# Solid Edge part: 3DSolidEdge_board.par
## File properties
Author: Administrator
Last saved by: Administrator
Revision: 49
Accuracy: 0.990
Agile_Description: Circuit Board
Modeled_By: L. Conard
Part_Number: ITEM-SE-00003
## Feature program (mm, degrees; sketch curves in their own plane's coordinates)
body "unnamed Body 1"
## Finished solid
Body 1: solid body, 16 faces, 42 edges, 28 vertices.
  Faces by surface: plane 9, cylinder 7
  Edges by curve: line 28, circle 14
Bounding box of the edges (mm): 59.250 x 100.960 x 2.000, from (0, 0, 0) to (59.25, 100.96, 2).
Cylindrical faces by radius (mm): R1.9 x3, R2.54 x4
Planar faces by outward normal: +x 2, +y 2, +z 1, -x 2, -y 1, -z 1
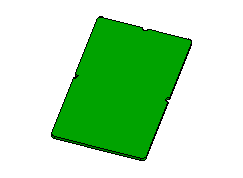
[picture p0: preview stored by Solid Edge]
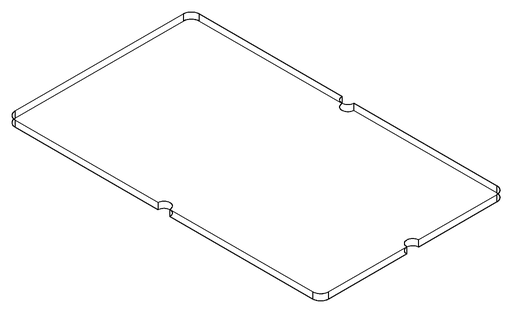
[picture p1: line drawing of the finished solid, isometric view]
